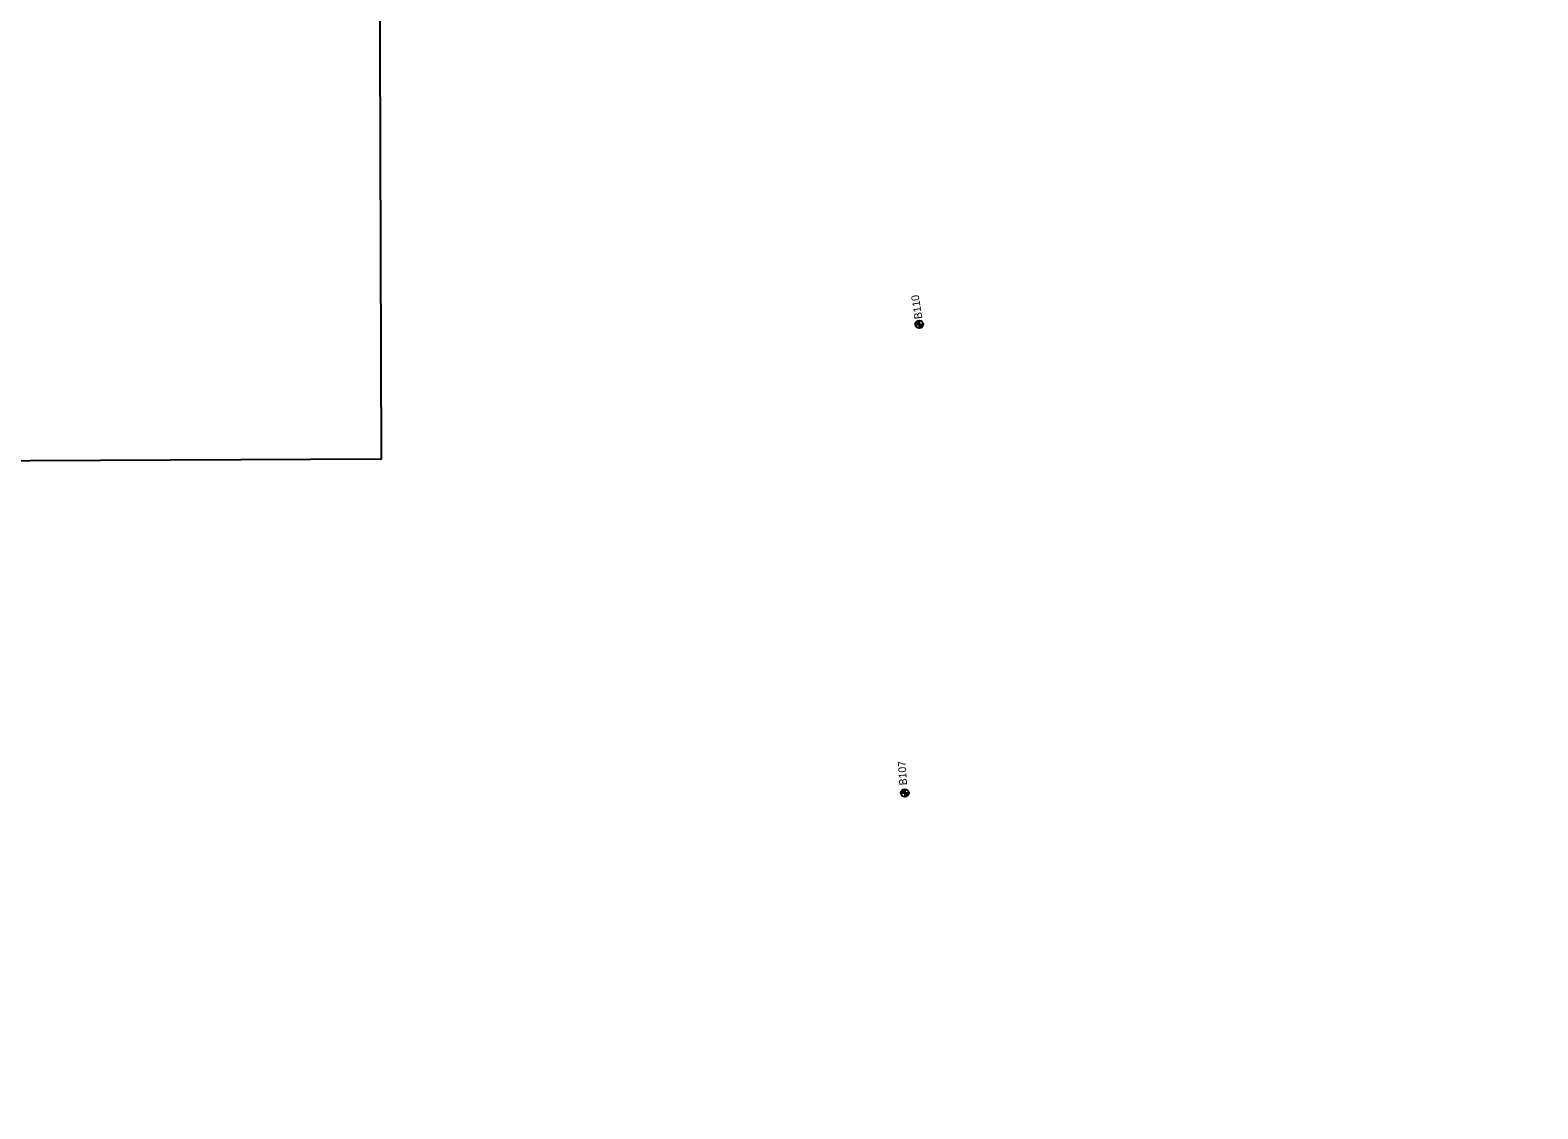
# Model space of a CAD drawing. Extents: x 331323 to 388339, y 121519 to 205315.
# Drawn here: x 354318 to 356257, y 187388 to 188776 of the extents above; entities that cross this region are included whole.
import ezdxf

# ---------------------------------------------------------------- set-up
doc = ezdxf.new("R2010")
doc.units = 0
for name, color, linetype in [('E_SOIL_BORE1 [KAPUR_CADDS_LEVELS]', 7, 'Continuous'), ('E_SOIL_BORE2 [KAPUR_CADDS_LEVELS]', 7, 'Continuous'), ('Level 21', 7, 'Continuous'), ('P_MARK', 7, 'Continuous')]:
    doc.layers.add(name, color=color, linetype=linetype)

msp = doc.modelspace()

# ---------------------------------------------------------------- linework, layer by layer
at = {"layer": 'Level 21'}
msp.add_lwpolyline([(357414.6, 189602.4), (354765.3, 189557.7), (354769.6, 188224), (353415.3, 188217.6), (353444.8, 186857.7), (350815.7, 186814.1), (350760.9, 190650.5), (350710.4, 190685.8), (350714.9, 190216.5), (350495.4, 190209.7), (350561, 190784.4), (350527.3, 190818.9), (350419.8, 190919.9), (350245.1, 190981.8), (350216.8, 190577.4), (350099.1, 190374.5), (349811.9, 190521.9), (349486.7, 190507.7)], dxfattribs=at)
at = {"layer": 'P_MARK'}
for p, q in [((355456.5, 188397.5), (355466.5, 188397.5)), ((355461.5, 188402.5), (355461.5, 188392.5)), ((355437.9, 187794.5), (355447.9, 187794.5)), ((355442.9, 187799.5), (355442.9, 187789.5))]:
    msp.add_line(p, q, dxfattribs=at)
for centre in [(355461.5, 188397.5), (355442.9, 187794.5)]:
    msp.add_circle(centre, 5, dxfattribs=at)
for centre, radius, start, end in [((355461.5, 188397.5), 4.5, 89.9869, 179.9869), ((355461.5, 188397.5), 4, 89.9869, 179.9869), ((355461.5, 188397.5), 3.5, 89.9869, 179.9869), ((355461.5, 188397.5), 3, 89.9869, 179.9869), ((355461.5, 188397.5), 2.5, 89.9869, 179.9869), ((355461.5, 188397.5), 2, 89.9869, 179.9869), ((355461.5, 188397.5), 1.5, 89.9869, 179.9869), ((355461.5, 188397.5), 1, 89.9869, 179.9869), ((355461.5, 188397.5), 0.5, 89.9869, 179.9869), ((355461.5, 188397.5), 4.5, 269.9869, 359.9869), ((355461.5, 188397.5), 4, 269.9869, 359.9869), ((355461.5, 188397.5), 3.5, 269.9869, 359.9869), ((355461.5, 188397.5), 3, 269.9869, 359.9869), ((355461.5, 188397.5), 2.5, 269.9869, 359.9869), ((355461.5, 188397.5), 2, 269.9869, 359.9869), ((355461.5, 188397.5), 1.5, 269.9869, 359.9869), ((355461.5, 188397.5), 1, 269.9869, 359.9869), ((355461.5, 188397.5), 0.5, 269.9869, 359.9869), ((355442.9, 187794.5), 4.5, 89.9869, 179.9869), ((355442.9, 187794.5), 4, 89.9869, 179.9869), ((355442.9, 187794.5), 3.5, 89.9869, 179.9869), ((355442.9, 187794.5), 3, 89.9869, 179.9869), ((355442.9, 187794.5), 2.5, 89.9869, 179.9869), ((355442.9, 187794.5), 2, 89.9869, 179.9869), ((355442.9, 187794.5), 1.5, 89.9869, 179.9869), ((355442.9, 187794.5), 1, 89.9869, 179.9869), ((355442.9, 187794.5), 0.5, 89.9869, 179.9869), ((355442.9, 187794.5), 4.5, 269.9869, 359.9869), ((355442.9, 187794.5), 4, 269.9869, 359.9869), ((355442.9, 187794.5), 3.5, 269.9869, 359.9869), ((355442.9, 187794.5), 3, 269.9869, 359.9869), ((355442.9, 187794.5), 2.5, 269.9869, 359.9869), ((355442.9, 187794.5), 2, 269.9869, 359.9869), ((355442.9, 187794.5), 1.5, 269.9869, 359.9869), ((355442.9, 187794.5), 1, 269.9869, 359.9869), ((355442.9, 187794.5), 0.5, 269.9869, 359.9869)]:
    msp.add_arc(centre, radius, start, end, dxfattribs=at)

# ---------------------------------------------------------------- texts
at = {"layer": 'E_SOIL_BORE1 [KAPUR_CADDS_LEVELS]'}
msp.add_text('B107', height=10, rotation=93.5868, dxfattribs=at).set_placement((355445.9, 187804.7))
at = {"layer": 'E_SOIL_BORE2 [KAPUR_CADDS_LEVELS]'}
msp.add_text('B110', height=10, rotation=98.957, dxfattribs=at).set_placement((355465.6, 188405.1))

doc.saveas('drawing.dxf')
